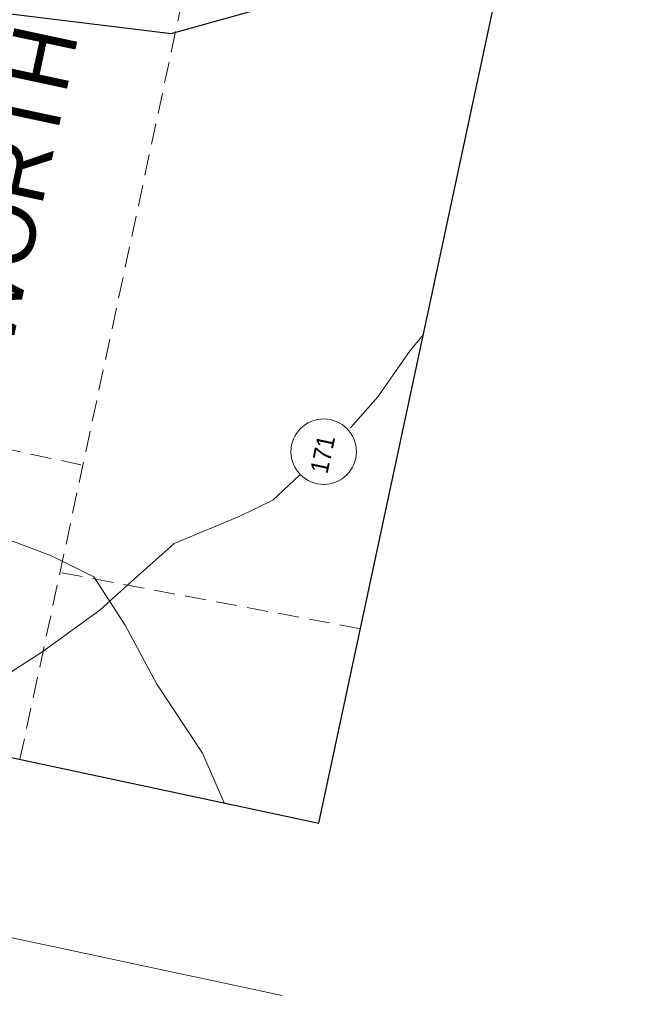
# Model space of a CAD drawing. Extents: x 2363411 to 2369126, y 6976878 to 6988319.
# Drawn here: x 2368374.1 to 2368553.7, y 6987708.3 to 6987987.6 of the extents above; entities that cross this region are included whole.
import ezdxf

# ---------------------------------------------------------------- set-up
doc = ezdxf.new("R2010")
doc.units = 0
doc.header["$LTSCALE"] = 2
doc.linetypes.add('MEDIUM_DASHED', pattern=[4.5, 3, -1.5])
for name, color, linetype, lineweight in [('40', 7, 'Continuous', 13), ('62', 7, 'Continuous', 13), ('63', 7, 'Continuous', 13)]:
    doc.layers.add(name, color=color, linetype=linetype, lineweight=lineweight)

msp = doc.modelspace()

# ---------------------------------------------------------------- linework, layer by layer
at = {"layer": '40'}
msp.add_line((2367663.763, 6987876.155), (2368449.239, 6987708.324), dxfattribs=at)
at = {"layer": '62', "linetype": 'MEDIUM_DASHED'}
for p, q in [((2368374.263, 6987775.914), (2368468.206, 6988215.584)), ((2368210.086, 6987898.986), (2368391.697, 6987860.206)), ((2368471.663, 6987813.273), (2368385.425, 6987829.445))]:
    msp.add_line(p, q, dxfattribs=at)
at = {"layer": '62'}
for p, q in [((2368476.652, 6987879.694), (2368468.827, 6987870.74)), ((2368446.578, 6987850.087), (2368454.218, 6987857.197)), ((2368437.149, 6987845.475), (2368446.578, 6987850.087))]:
    msp.add_line(p, q, dxfattribs=at)
at = {"layer": '62', "lineweight": 25}
for points in [[(2368004.774, 6987854.862), (2368459.776, 6987757.642), (2368553.719, 6988197.31), (2368098.715, 6988294.53)], [(2368243.911, 6988012.604), (2368291.866, 6988003.347), (2368346.556, 6987992.355), (2368417.518, 6987983.635), (2368451.697, 6987993.151)]]:
    msp.add_lwpolyline(points, dxfattribs=at)
at = {"layer": '62'}
for points in [[(2368476.652, 6987879.694), (2368485.823, 6987892.899), (2368489.662, 6987897.509)], [(2368316.854, 6987788.182), (2368322.138, 6987790.941), (2368338.721, 6987798.237), (2368356.354, 6987799.347), (2368370.57, 6987800.198), (2368380.507, 6987806.541), (2368397.068, 6987818.558), (2368405.207, 6987825.955), (2368418.347, 6987837.711), (2368437.149, 6987845.475)], [(2368370.893, 6987838.853), (2368383.263, 6987834.188), (2368395.397, 6987828.188), (2368404.391, 6987814.277), (2368413.364, 6987797.381), (2368426.436, 6987777.677), (2368432.622, 6987763.444)]]:
    msp.add_lwpolyline(points, dxfattribs=at)
msp.add_circle((2368461.127, 6987863.964), 9.364, dxfattribs=at)
at = {"layer": '63', "linetype": 'MEDIUM_DASHED'}
for p, q in [((2368374.263, 6987775.914), (2368468.206, 6988215.584)), ((2368210.086, 6987898.986), (2368391.697, 6987860.206)), ((2368471.663, 6987813.273), (2368385.425, 6987829.445))]:
    msp.add_line(p, q, dxfattribs=at)
at = {"layer": '63'}
for p, q in [((2368476.652, 6987879.694), (2368468.827, 6987870.74)), ((2368446.578, 6987850.087), (2368454.218, 6987857.197)), ((2368437.149, 6987845.475), (2368446.578, 6987850.087))]:
    msp.add_line(p, q, dxfattribs=at)
at = {"layer": '63', "lineweight": 25}
for points in [[(2368004.774, 6987854.862), (2368459.776, 6987757.642), (2368553.719, 6988197.31), (2368098.715, 6988294.53)], [(2368243.911, 6988012.604), (2368291.866, 6988003.347), (2368346.556, 6987992.355), (2368417.518, 6987983.635), (2368451.697, 6987993.151)]]:
    msp.add_lwpolyline(points, dxfattribs=at)
at = {"layer": '63'}
for points in [[(2368476.652, 6987879.694), (2368485.823, 6987892.899), (2368489.662, 6987897.509)], [(2368316.854, 6987788.182), (2368322.138, 6987790.941), (2368338.721, 6987798.237), (2368356.354, 6987799.347), (2368370.57, 6987800.198), (2368380.507, 6987806.541), (2368397.068, 6987818.558), (2368405.207, 6987825.955), (2368418.347, 6987837.711), (2368437.149, 6987845.475)], [(2368370.893, 6987838.853), (2368383.263, 6987834.188), (2368395.397, 6987828.188), (2368404.391, 6987814.277), (2368413.364, 6987797.381), (2368426.436, 6987777.677), (2368432.622, 6987763.444)]]:
    msp.add_lwpolyline(points, dxfattribs=at)
msp.add_circle((2368461.127, 6987863.964), 9.364, dxfattribs=at)

# ---------------------------------------------------------------- texts
at = {"layer": '62'}
msp.add_text('WORTH', height=18.39, rotation=77.939, dxfattribs=at).set_placement((2368371.617, 6987892.428))
at = {"layer": '62', "width": 0.95}
msp.add_text('171', height=5.099, rotation=77.939, dxfattribs=at).set_placement((2368462.173, 6987857.386))
at = {"layer": '63'}
msp.add_text('WORTH', height=18.39, rotation=77.939, dxfattribs=at).set_placement((2368371.617, 6987892.428))
at = {"layer": '63', "width": 0.95}
msp.add_text('171', height=5.099, rotation=77.939, dxfattribs=at).set_placement((2368462.173, 6987857.386))

doc.saveas('drawing.dxf')
